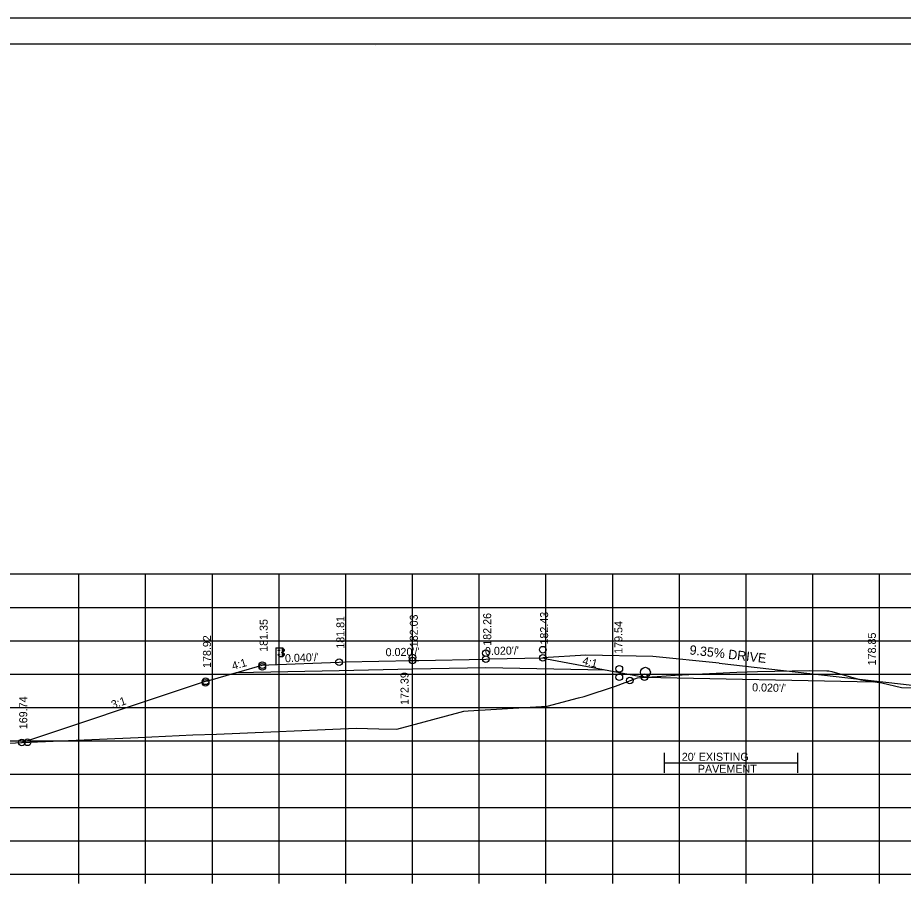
# Model space of a CAD drawing. Extents: x 915787 to 919910, y 133456 to 136717.
# Drawn here: x 916354.8 to 916487.5, y 135459 to 135589.4 of the extents above; entities that cross this region are included whole.
import ezdxf

# ---------------------------------------------------------------- set-up
doc = ezdxf.new("R2010")
doc.units = 0
for name, color, linetype in [('R_Axis', 7, 'Continuous'), ('R_Border', 7, 'Continuous'), ('R_Drive', 7, 'Continuous'), ('R_Exist Surface', 7, 'Continuous'), ('R_Exist Surface Annot', 7, 'Continuous'), ('R_Fin Surface', 7, 'Continuous'), ('R_Grid', 7, 'Continuous'), ('R_No Plot', 7, 'Continuous'), ('R_Proposed Road', 7, 'Continuous'), ('R_Water', 7, 'Continuous'), ('R_Xsect Elev', 7, 'Continuous'), ('R_Xsect Slope', 7, 'Continuous')]:
    doc.layers.add(name, color=color, linetype=linetype)

msp = doc.modelspace()

# ---------------------------------------------------------------- linework, layer by layer
at = {"layer": 'R_Axis'}
for p, q in [((916273.98, 135461.06), (916553.98, 135461.06)), ((916363.98, 135459.66), (916363.98, 135461.06)), ((916373.98, 135459.66), (916373.98, 135461.06)), ((916383.98, 135459.66), (916383.98, 135461.06)), ((916393.98, 135459.66), (916393.98, 135461.06)), ((916403.98, 135459.66), (916403.98, 135461.06)), ((916413.98, 135459.66), (916413.98, 135461.06)), ((916423.98, 135459.66), (916423.98, 135461.06)), ((916433.98, 135459.66), (916433.98, 135461.06)), ((916443.98, 135459.66), (916443.98, 135461.06)), ((916453.98, 135459.66), (916453.98, 135461.06)), ((916463.98, 135459.66), (916463.98, 135461.06)), ((916473.98, 135459.66), (916473.98, 135461.06)), ((916483.98, 135459.66), (916483.98, 135461.06))]:
    msp.add_line(p, q, dxfattribs=at)
at = {"layer": 'R_Border'}
for p, q in [((916255.98, 135585.52), (916572.16, 135585.52)), ((916408.5, 135585.26), (916408.5, 135585.26)), ((916408.5, 135585.26), (916408.5, 135585.26))]:
    msp.add_line(p, q, dxfattribs=at)
at = {"layer": 'R_Drive'}
for p, q in [((916439.97, 135493.88), (916433.5, 135493.49)), ((916449.97, 135493.69), (916439.97, 135493.88)), ((916459.92, 135492.7), (916449.97, 135493.69)), ((916459.92, 135492.7), (916494.19, 135488.81))]:
    msp.add_line(p, q, dxfattribs=at)
at = {"layer": 'R_Exist Surface'}
msp.add_lwpolyline([(916350.5, 135480.54), (916355.47, 135480.8), (916372.87, 135481.57), (916381.04, 135481.94), (916384.59, 135482.08), (916405.54, 135482.94), (916408.92, 135482.87), (916411.61, 135482.81), (916421.12, 135485.36), (916421.69, 135485.5), (916422.3, 135485.54), (916434.17, 135486.26), (916438.86, 135487.48), (916439.71, 135487.71), (916444.42, 135489.27), (916447.69, 135490.52), (916448.98, 135490.61), (916450.64, 135490.71), (916453.35, 135490.9), (916462.58, 135491.37), (916465.69, 135491.45), (916473.47, 135491.61), (916476.08, 135491.57), (916476.39, 135491.55), (916476.84, 135491.44), (916481.17, 135490.19), (916484.3, 135489.73), (916487.25, 135489.05), (916498.38, 135488.8)], dxfattribs=at)
at = {"layer": 'R_Exist Surface Annot'}
for p, q in [((916451.69, 135479.27), (916451.69, 135476.27)), ((916471.69, 135479.27), (916471.69, 135476.27)), ((916451.69, 135477.77), (916471.69, 135477.77))]:
    msp.add_line(p, q, dxfattribs=at)
at = {"layer": 'R_Fin Surface'}
for points in [[(916355.44, 135480.8), (916380.72, 135489.23), (916382.97, 135489.98), (916383.31, 135490.06), (916387.6, 135491.3), (916387.98, 135491.4), (916391.47, 135492.4), (916392.44, 135492.44), (916402.97, 135492.86), (916403.9, 135492.89), (916413.97, 135493.09), (916414.9, 135493.11), (916424.97, 135493.31), (916425.48, 135493.33), (916433.5, 135493.49), (916434.06, 135493.35), (916448.74, 135490.6), (916483.06, 135489.91)], [(916387.6, 135491.3), (916402.97, 135491.61), (916413.97, 135491.84), (916424.97, 135492.06), (916442.82, 135491.71)]]:
    msp.add_lwpolyline(points, dxfattribs=at)
at = {"layer": 'R_Grid'}
for p, q in [((916273.98, 135506.06), (916553.98, 135506.06)), ((916363.98, 135461.06), (916363.98, 135506.06)), ((916373.98, 135461.06), (916373.98, 135506.06)), ((916383.98, 135461.06), (916383.98, 135506.06)), ((916393.98, 135461.06), (916393.98, 135506.06)), ((916403.98, 135461.06), (916403.98, 135506.06)), ((916413.98, 135461.06), (916413.98, 135506.06)), ((916423.98, 135461.06), (916423.98, 135506.06)), ((916433.98, 135461.06), (916433.98, 135506.06)), ((916443.98, 135461.06), (916443.98, 135506.06)), ((916453.98, 135461.06), (916453.98, 135506.06)), ((916463.98, 135461.06), (916463.98, 135506.06)), ((916473.98, 135461.06), (916473.98, 135506.06)), ((916483.98, 135461.06), (916483.98, 135506.06)), ((916273.98, 135501.06), (916553.98, 135501.06)), ((916273.98, 135496.06), (916553.98, 135496.06)), ((916273.98, 135491.06), (916553.98, 135491.06)), ((916273.98, 135486.06), (916553.98, 135486.06)), ((916273.98, 135481.06), (916553.98, 135481.06)), ((916273.98, 135476.06), (916553.98, 135476.06)), ((916273.98, 135471.06), (916553.98, 135471.06)), ((916273.98, 135466.06), (916553.98, 135466.06)), ((916273.98, 135461.06), (916553.98, 135461.06))]:
    msp.add_line(p, q, dxfattribs=at)
at = {"layer": 'R_No Plot'}
msp.add_line((916243.57, 135589.41), (916576.91, 135589.41), dxfattribs=at)
for points in [[(916243.57, 135589.41), (916576.91, 135589.41), (916576.91, 135376.07), (916243.57, 135376.07)], [(916489.9, 135585.52), (916489.9, 135575.64), (916525.63, 135575.64), (916525.63, 135572.72), (916548.83, 135572.72), (916548.83, 135549.5), (916572.16, 135549.5), (916572.16, 135380.06), (916255.98, 135380.06), (916255.98, 135585.52)]]:
    msp.add_lwpolyline(points, close=True, dxfattribs=at)
for centre in [(916424.97, 135494.2), (916433.5, 135494.72), (916402.97, 135492.86), (916402.97, 135492.86), (916413.97, 135493.53), (916413.97, 135493.09), (916424.97, 135493.31), (916433.5, 135493.49), (916391.47, 135492.4), (916391.47, 135492.16), (916444.97, 135491.85), (916444.97, 135490.62), (916448.74, 135490.6), (916382.97, 135489.98), (916382.97, 135489.74), (916446.55, 135490.09), (916355.44, 135480.8), (916356.27, 135480.84)]:
    msp.add_circle(centre, 0.5, dxfattribs=at)
at = {"layer": 'R_Proposed Road'}
for p, q in [((916393.47, 135495), (916393.47, 135492.48)), ((916393.5, 135495), (916393.5, 135492.48)), ((916393.87, 135494.59), (916393.87, 135494.68)), ((916393.93, 135494.69), (916393.88, 135494.69)), ((916393.93, 135494.66), (916393.88, 135494.66)), ((916394, 135495), (916393.93, 135494.99)), ((916393.93, 135494.57), (916393.93, 135494.69)), ((916393.97, 135492.48), (916393.97, 135495)), ((916394, 135495), (916393.99, 135495)), ((916394.05, 135494.63), (916394, 135494.63)), ((916394.01, 135494.69), (916394.06, 135494.69)), ((916394.06, 135494.69), (916394.06, 135494.56)), ((916394.5, 135493.63), (916394.5, 135494.99)), ((916394.64, 135494.78), (916394.53, 135494.84)), ((916394.63, 135494.77), (916394.54, 135494.82)), ((916394.76, 135494.66), (916394.63, 135494.77)), ((916394.77, 135494.68), (916394.64, 135494.78)), ((916393.86, 135493.9), (916393.86, 135493.99)), ((916393.92, 135494.01), (916393.87, 135494.01)), ((916393.92, 135493.97), (916393.87, 135493.97)), ((916393.92, 135493.91), (916393.87, 135493.91)), ((916393.92, 135493.88), (916393.87, 135493.88)), ((916393.93, 135494.6), (916393.88, 135494.6)), ((916393.93, 135494.57), (916393.88, 135494.57)), ((916393.92, 135493.91), (916393.88, 135493.91)), ((916393.93, 135494.6), (916393.89, 135494.6)), ((916393.92, 135493.88), (916393.92, 135494.01)), ((916394, 135493.63), (916393.96, 135493.63)), ((916394.05, 135493.94), (916394, 135493.94)), ((916394.01, 135494.56), (916394.06, 135494.56)), ((916394.06, 135494.01), (916394.01, 135494.01)), ((916394.06, 135493.88), (916394.01, 135493.88)), ((916394.06, 135493.88), (916394.06, 135494.01)), ((916394.43, 135494.26), (916394.43, 135494.36)), ((916394.49, 135494.37), (916394.44, 135494.37)), ((916394.49, 135494.34), (916394.44, 135494.34)), ((916394.49, 135494.28), (916394.44, 135494.28)), ((916394.49, 135494.28), (916394.44, 135494.28)), ((916394.49, 135494.25), (916394.44, 135494.25)), ((916394.49, 135494.25), (916394.49, 135494.37)), ((916394.53, 135493.79), (916394.63, 135493.85)), ((916394.53, 135493.77), (916394.65, 135493.83)), ((916394.54, 135494.25), (916394.54, 135494.38)), ((916394.56, 135494.25), (916394.56, 135494.38)), ((916394.58, 135494.45), (916394.76, 135494.55)), ((916394.73, 135494.08), (916394.58, 135494.17)), ((916394.75, 135494.1), (916394.59, 135494.19)), ((916394.6, 135494.43), (916394.77, 135494.53)), ((916394.63, 135493.85), (916394.76, 135493.96)), ((916394.65, 135493.83), (916394.77, 135493.94))]:
    msp.add_line(p, q, dxfattribs=at)
msp.add_lwpolyline([(916393.47, 135495), (916393.93, 135494.99), (916393.93, 135492.48)], dxfattribs=at)
for points in [[(916393.87, 135494.66), (916393.87, 135494.6), (916393.85, 135494.6), (916393.85, 135494.66)], [(916393.93, 135494.71), (916393.93, 135494.55), (916393.94, 135494.55), (916393.94, 135494.71)], [(916394.52, 135495), (916394.52, 135493.63), (916394, 135493.63), (916394, 135495)], [(916394.05, 135494.69), (916394.05, 135494.56), (916394, 135494.56), (916394, 135494.69)], [(916393.86, 135493.97), (916393.86, 135493.91), (916393.84, 135493.91), (916393.84, 135493.97)], [(916393.92, 135494.03), (916393.92, 135493.86), (916393.93, 135493.86), (916393.93, 135494.03)], [(916394.05, 135494.01), (916394.05, 135493.88), (916394, 135493.88), (916394, 135494.01)], [(916394.43, 135494.34), (916394.43, 135494.28), (916394.4, 135494.28), (916394.4, 135494.34)], [(916394.48, 135494.39), (916394.48, 135494.23), (916394.49, 135494.23), (916394.49, 135494.39)]]:
    msp.add_lwpolyline(points, close=True, dxfattribs=at)
for centre, radius, start, end in [((916393.9, 135494.68), 0.022, 134.5745, 222.2244), ((916393.97, 135494.63), 0.0922, 159.7423, 200.2577), ((916394.73, 135494.61), 0.062, 299.2499, 57.9783), ((916394.73, 135494.61), 0.0856, 299.2499, 57.9783), ((916393.89, 135493.99), 0.022, 134.5745, 222.2244), ((916393.96, 135493.94), 0.0922, 159.7423, 200.2577), ((916393.89, 135493.9), 0.025, 140.9334, 216.6234), ((916393.9, 135494.58), 0.025, 140.9334, 216.6234), ((916394.45, 135494.36), 0.022, 134.5745, 222.2244), ((916394.52, 135494.31), 0.0922, 159.7423, 200.2577), ((916394.46, 135494.26), 0.025, 140.9334, 216.6234), ((916394.63, 135494.37), 0.0865, 118.106, 175.0444), ((916394.61, 135494.24), 0.0703, 171.7804, 246.8536), ((916394.63, 135494.37), 0.0622, 118.106, 175.0444), ((916394.56, 135494.31), 0.0453, 282.9554, 86.0697), ((916394.61, 135494.24), 0.0462, 171.7804, 246.8536), ((916394.69, 135494), 0.0854, 325.2184, 59.12), ((916394.69, 135494), 0.109, 325.2184, 59.12)]:
    msp.add_arc(centre, radius, start, end, dxfattribs=at)
at = {"layer": 'R_Water'}
msp.add_line((916448.74, 135490.6), (916483.06, 135489.91), dxfattribs=at)
msp.add_circle((916448.87, 135491.33), 0.75, dxfattribs=at)

# ---------------------------------------------------------------- texts
at = {"layer": 'R_Drive'}
msp.add_text('9.35% DRIVE', height=1.4, rotation=353.5147, dxfattribs=at).set_placement((916455.44, 135494.02))
at = {"layer": 'R_Exist Surface Annot'}
for s, p in [("20' EXISTING", (916454.33, 135478.07)), ('PAVEMENT', (916456.74, 135476.27))]:
    msp.add_text(s, height=1.2, dxfattribs=at).set_placement(p)
at = {"layer": 'R_Xsect Elev'}
for s, p in [('182.03', (916414.77, 135495.09)), ('182.26', (916425.77, 135495.31)), ('182.43', (916434.3, 135495.49)), ('181.35', (916392.27, 135494.4)), ('181.81', (916403.77, 135494.86)), ('179.54', (916445.43, 135494.1)), ('178.92', (916383.77, 135491.98)), ('178.85', (916483.42, 135492.37)), ('172.39', (916413.38, 135486.44)), ('169.74', (916356.24, 135482.8))]:
    msp.add_text(s, height=1.2, rotation=90, dxfattribs=at).set_placement(p)
at = {"layer": 'R_Xsect Slope'}
for s, rotation, p in [("0.020'/'", 1.1711, (916409.96, 135493.73)), ("0.020'/'", 1.1636, (916424.85, 135493.91)), ('4:1', 15.9296, (916387.09, 135491.67)), ("0.040'/'", 2.2906, (916394.89, 135492.83)), ('4:1', 345.9638, (916439.36, 135492.54)), ("0.020'/'", 358.8542, (916464.86, 135488.48)), ('3:1', 18.4349, (916369.05, 135485.86))]:
    msp.add_text(s, height=1.2, rotation=rotation, dxfattribs=at).set_placement(p)

doc.saveas('drawing.dxf')
